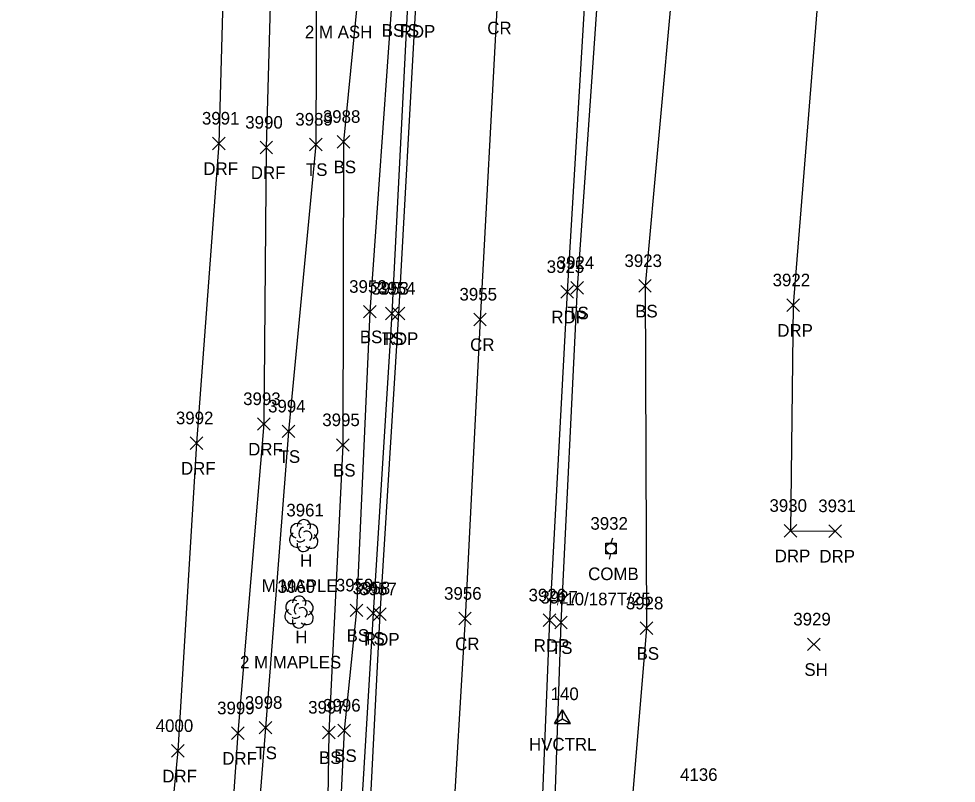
# Model space of a CAD drawing. Extents: x 1678863 to 1683592, y 407783 to 418211.
# Drawn here: x 1680263.1 to 1680411.8, y 413639.6 to 413760.9 of the extents above; entities that cross this region are included whole.
import ezdxf

# ---------------------------------------------------------------- set-up
doc = ezdxf.new("R2010")
doc.units = 0
for name, color, linetype in [('C_A', 7, 'Continuous'), ('C_I', 7, 'Continuous'), ('CPSM', 7, 'Continuous'), ('L_A', 7, 'Continuous'), ('L_C', 7, 'Continuous'), ('L_I', 7, 'Continuous'), ('L_TIC', 7, 'Continuous'), ('LELB', 7, 'Continuous'), ('LTD', 7, 'Continuous'), ('P_A', 7, 'Continuous'), ('P_I', 7, 'Continuous'), ('P_TIC', 7, 'Continuous'), ('PET', 7, 'Continuous'), ('PRC', 7, 'Continuous'), ('R_A', 7, 'Continuous'), ('R_I', 7, 'Continuous'), ('R_TIC', 7, 'Continuous'), ('RDF', 7, 'Continuous'), ('RDP', 7, 'Continuous'), ('U_A', 7, 'Continuous'), ('U_C', 7, 'Continuous'), ('U_I', 7, 'Continuous'), ('UP', 7, 'Continuous')]:
    doc.layers.add(name, color=color, linetype=linetype)

msp = doc.modelspace()

# ---------------------------------------------------------------- linework, layer by layer
at = {"layer": 'CPSM'}
for p, q in [((1680348.09, 413649.08), (1680349.34, 413651.25)), ((1680350.59, 413649.08), (1680349.34, 413651.25)), ((1680349.34, 413649.8), (1680349.34, 413651.25)), ((1680348.09, 413649.08), (1680349.34, 413649.8)), ((1680349.34, 413649.8), (1680349.34, 413649.8)), ((1680349.34, 413649.8), (1680350.59, 413649.08)), ((1680348.09, 413649.08), (1680350.59, 413649.08))]:
    msp.add_line(p, q, dxfattribs=at)
at = {"layer": 'L_TIC'}
for points in [[(1680309.23, 413739.98), (1680311.23, 413741.98)], [(1680311.23, 413739.98), (1680309.23, 413741.98)], [(1680313.59, 413740.41), (1680315.59, 413742.41)], [(1680315.59, 413740.41), (1680313.59, 413742.41)], [(1680361.43, 413717.53), (1680363.43, 413719.53)], [(1680363.43, 413717.53), (1680361.43, 413719.53)], [(1680350.69, 413717.23), (1680352.69, 413719.23)], [(1680352.69, 413717.23), (1680350.69, 413719.23)], [(1680317.76, 413713.44), (1680319.76, 413715.44)], [(1680319.76, 413713.44), (1680317.76, 413715.44)], [(1680321.28, 413713.15), (1680323.28, 413715.15)], [(1680323.28, 413713.15), (1680321.28, 413715.15)], [(1680304.9, 413694.45), (1680306.9, 413696.45)], [(1680306.9, 413694.45), (1680304.9, 413696.45)], [(1680313.5, 413692.28), (1680315.5, 413694.28)], [(1680315.5, 413692.28), (1680313.5, 413694.28)], [(1680315.65, 413666.05), (1680317.65, 413668.05)], [(1680317.65, 413666.05), (1680315.65, 413668.05)], [(1680318.32, 413665.59), (1680320.32, 413667.59)], [(1680320.32, 413665.59), (1680318.32, 413667.59)], [(1680348.1, 413664.12), (1680350.1, 413666.12)], [(1680350.1, 413664.12), (1680348.1, 413666.12)], [(1680361.65, 413663.2), (1680363.65, 413665.2)], [(1680363.65, 413663.2), (1680361.65, 413665.2)], [(1680388.22, 413660.65), (1680390.22, 413662.65)], [(1680390.22, 413660.65), (1680388.22, 413662.65)], [(1680301.22, 413647.42), (1680303.22, 413649.42)], [(1680303.22, 413647.42), (1680301.22, 413649.42)], [(1680311.26, 413646.66), (1680313.26, 413648.66)], [(1680313.26, 413646.66), (1680311.26, 413648.66)], [(1680313.69, 413646.98), (1680315.69, 413648.98)], [(1680315.69, 413646.98), (1680313.69, 413648.98)]]:
    msp.add_lwpolyline(points, dxfattribs=at)
at = {"layer": 'LELB'}
for points in [[(1680328.8, 414196.16), (1680329.42, 414154.35), (1680329.9, 414108.73), (1680324.37, 414065.09), (1680323.69, 414045.18), (1680321.93, 414011.62), (1680327.59, 413969.26), (1680329.3, 413913), (1680328.66, 413864.29), (1680326.97, 413811.9), (1680324.77, 413763.09), (1680322.28, 413714.15), (1680319.32, 413666.59), (1680317.19, 413631.47), (1680315.04, 413584.83), (1680311.9, 413541.88), (1680311.77, 413525.72)], [(1680333.49, 414185.64), (1680335.28, 414154.34), (1680335.31, 414108.58), (1680333.17, 414064.14), (1680332.9, 414010.98), (1680327.01, 414005.42), (1680327.59, 413969.26), (1680324.87, 413913.45), (1680326.11, 413864.17), (1680324.22, 413811.96), (1680322.23, 413763.08), (1680318.76, 413714.44), (1680316.65, 413667.05), (1680314.69, 413647.98), (1680313.33, 413619.55), (1680312.59, 413608.22), (1680310.92, 413608.34)], [(1680310.3, 413964.45), (1680313.38, 413925.26), (1680313.62, 413870.17), (1680310.5, 413836.3), (1680310.39, 413783.38), (1680310.23, 413740.98), (1680305.9, 413695.45), (1680302.22, 413648.42), (1680299.26, 413611.53), (1680297.37, 413601.66), (1680307.54, 413597.2), (1680308.18, 413584.58), (1680306.18, 413542.36), (1680304.07, 413518.67), (1680292.7, 413506.12)], [(1680410.49, 413871.95), (1680391.22, 413872.57), (1680366.56, 413871.7), (1680360.91, 413867.94), (1680361.47, 413861.16), (1680357.56, 413819.52), (1680355.15, 413768.47), (1680351.69, 413718.23), (1680349.1, 413665.12), (1680348.01, 413633.93), (1680345.49, 413592.28), (1680344.55, 413583.78), (1680350.55, 413572.29), (1680354.65, 413565.16)], [(1680411.8, 413856.83), (1680388.37, 413856.64), (1680367.47, 413857.06), (1680366.7, 413818.76), (1680366.79, 413766.4), (1680362.43, 413718.53), (1680362.65, 413664.2), (1680360.05, 413633.04), (1680379.39, 413591.61)], [(1680315.59, 413837.65), (1680318.63, 413782.24), (1680314.59, 413741.41), (1680314.5, 413693.28), (1680312.26, 413647.66), (1680311.86, 413619.89), (1680310.92, 413608.34)]]:
    msp.add_lwpolyline(points, dxfattribs=at)
at = {"layer": 'LTD'}
for p, q in [((1680308.28, 413678.95), (1680308.28, 413678.95)), ((1680308.28, 413678.95), (1680308.28, 413678.95)), ((1680307.53, 413666.82), (1680307.53, 413666.82)), ((1680307.53, 413666.82), (1680307.53, 413666.82))]:
    msp.add_line(p, q, dxfattribs=at)
for centre in [(1680308.32, 413680.39), (1680307.58, 413668.25)]:
    msp.add_arc(centre, 1.05, 335.5272, 180.9563, dxfattribs=at)
for centre, major_axis, ratio, start_param, end_param in [((1680307.48, 413679.62), (1.21, -0.51), 0.895232, 1.570796, 4.712389), ((1680309.32, 413679.54), (-1.14, -0.48), 0.949671, 1.570796, 4.712389), ((1680307.19, 413678.24), (0.58, -1.04), 0.959034, 3.141593, 6.283185), ((1680308.07, 413679.41), (-0.208, -0.792), 0.645439, 3.141593, 6.283185), ((1680308.78, 413678.79), (-0.5, 0.667), 0.989748, 3.141593, 6.283185), ((1680307.82, 413678.2), (-0.625, -0.083), 0.423636, 0, 3.141593), ((1680309.28, 413678.12), (-1.09, 0.79), 0.841452, 1.570796, 4.712389), ((1680308.28, 413677.45), (0.26, 1.06), 0.942809, 1.570796, 4.712389), ((1680306.74, 413667.48), (1.21, -0.51), 0.895232, 1.570796, 4.712389), ((1680307.32, 413667.28), (-0.208, -0.792), 0.645439, 3.141593, 6.283185), ((1680308.03, 413666.65), (-0.5, 0.667), 0.989748, 3.141593, 6.283185), ((1680308.57, 413667.4), (-1.14, -0.48), 0.949671, 1.570796, 4.712389), ((1680306.45, 413666.11), (0.58, -1.04), 0.959034, 3.141593, 6.283185), ((1680307.07, 413666.07), (-0.625, -0.083), 0.423636, 0, 3.141593), ((1680308.53, 413665.98), (-1.09, 0.79), 0.841452, 1.570796, 4.712389), ((1680307.53, 413665.32), (0.26, 1.06), 0.942809, 1.570796, 4.712389)]:
    msp.add_ellipse(centre, major_axis=major_axis, ratio=ratio, start_param=start_param, end_param=end_param, dxfattribs=at)
at = {"layer": 'P_TIC'}
for points in [[(1680349.09, 413716.59), (1680351.09, 413718.59)], [(1680351.09, 413716.59), (1680349.09, 413718.59)], [(1680322.35, 413713.16), (1680324.35, 413715.16)], [(1680324.35, 413713.16), (1680322.35, 413715.16)], [(1680335.26, 413712.21), (1680337.26, 413714.21)], [(1680337.26, 413712.21), (1680335.26, 413714.21)], [(1680319.37, 413665.45), (1680321.37, 413667.45)], [(1680321.37, 413665.45), (1680319.37, 413667.45)], [(1680332.88, 413664.73), (1680334.88, 413666.73)], [(1680334.88, 413664.73), (1680332.88, 413666.73)], [(1680346.28, 413664.47), (1680348.28, 413666.47)], [(1680348.28, 413664.47), (1680346.28, 413666.47)]]:
    msp.add_lwpolyline(points, dxfattribs=at)
at = {"layer": 'PET'}
for points in [[(1680337.74, 414063.85), (1680336.89, 414010.83), (1680335.53, 413968.42), (1680333.05, 413912.65), (1680330.57, 413864.02), (1680327.9, 413811.73), (1680326.03, 413762.93), (1680323.35, 413714.16), (1680320.37, 413666.45), (1680318.55, 413631.25), (1680316.14, 413584.69), (1680313.68, 413541.42), (1680312.42, 413523.36), (1680310.1, 413497.18), (1680310.27, 413479.23), (1680309.45, 413465.43), (1680306.28, 413414.4), (1680304.56, 413390.73), (1680303.5, 413367.03), (1680300.17, 413323.12), (1680296.71, 413266.44), (1680294.23, 413226.16), (1680292.89, 413196.25), (1680291.23, 413147.08)], [(1680365.04, 414025.12), (1680363.57, 413992.05), (1680361.98, 413945.68), (1680359.55, 413895.48), (1680358.76, 413869.12), (1680357.89, 413860.66), (1680355.72, 413819.25), (1680353.15, 413768.91), (1680350.09, 413717.59), (1680347.28, 413665.47), (1680345.99, 413633.9), (1680343.8, 413592.27), (1680342.77, 413574.68), (1680340.07, 413539.43), (1680339.13, 413515.37), (1680337.39, 413483.26), (1680333.74, 413422.22), (1680332.43, 413393.84), (1680331.39, 413363.68), (1680328.51, 413328.7), (1680325.07, 413264.49), (1680323.24, 413225.37), (1680321.3, 413184.73)]]:
    msp.add_lwpolyline(points, dxfattribs=at)
at = {"layer": 'PRC'}
msp.add_lwpolyline([(1680351.68, 414063.47), (1680351.07, 414011.17), (1680349.92, 413968.85), (1680347.07, 413911.41), (1680344.67, 413863.93), (1680341.49, 413810.97), (1680338.98, 413763.46), (1680336.26, 413713.21), (1680333.88, 413665.73), (1680331.73, 413629.34), (1680329.35, 413585.64), (1680326.79, 413539.67), (1680324.56, 413493.26), (1680322.55, 413462.88), (1680320.16, 413417.83), (1680318.29, 413388.45), (1680316.89, 413365.1), (1680314.19, 413322.55), (1680311.04, 413264.13), (1680308.9, 413226.32), (1680307.27, 413195.54), (1680304.84, 413145.79)], dxfattribs=at)
at = {"layer": 'R_TIC'}
for points in [[(1680293.84, 413740.14), (1680295.84, 413742.14)], [(1680295.84, 413740.14), (1680293.84, 413742.14)], [(1680301.36, 413739.49), (1680303.36, 413741.49)], [(1680303.36, 413739.49), (1680301.36, 413741.49)], [(1680384.93, 413714.47), (1680386.93, 413716.47)], [(1680386.93, 413714.47), (1680384.93, 413716.47)], [(1680300.95, 413695.62), (1680302.95, 413697.62)], [(1680302.95, 413695.62), (1680300.95, 413697.62)], [(1680290.28, 413692.58), (1680292.28, 413694.58)], [(1680292.28, 413692.58), (1680290.28, 413694.58)], [(1680384.52, 413678.68), (1680386.52, 413680.68)], [(1680386.52, 413678.68), (1680384.52, 413680.68)], [(1680391.6, 413678.63), (1680393.6, 413680.63)], [(1680393.6, 413678.63), (1680391.6, 413680.63)], [(1680296.83, 413646.55), (1680298.83, 413648.55)], [(1680298.83, 413646.55), (1680296.83, 413648.55)], [(1680287.32, 413643.74), (1680289.32, 413645.74)], [(1680289.32, 413643.74), (1680287.32, 413645.74)]]:
    msp.add_lwpolyline(points, dxfattribs=at)
at = {"layer": 'RDF'}
for points in [[(1680293.38, 413994.57), (1680304.05, 413962.38), (1680306.31, 413925.24), (1680306.07, 413871.28), (1680307.56, 413836.62), (1680303.79, 413791.26), (1680302.36, 413740.49), (1680301.95, 413696.62), (1680297.83, 413647.55), (1680295.14, 413608.28), (1680287.08, 413579.47)], [(1680285.71, 413990.78), (1680295.95, 413964.17), (1680298.49, 413925.92), (1680297.85, 413873.11), (1680298.81, 413841.35), (1680296.33, 413794.3), (1680294.84, 413741.14), (1680291.28, 413693.58), (1680288.32, 413644.74), (1680285.28, 413613.34), (1680275.4, 413582.62), (1680263.09, 413554.99)]]:
    msp.add_lwpolyline(points, dxfattribs=at)
at = {"layer": 'RDP'}
msp.add_lwpolyline([(1680410.39, 413843.14), (1680396.21, 413836.2), (1680392.99, 413818.96), (1680390.07, 413766.83), (1680385.93, 413715.47), (1680385.52, 413679.68), (1680392.6, 413679.63)], dxfattribs=at)
at = {"layer": 'UP'}
for p, q in [((1680357.28, 413678.51), (1680357.03, 413677.68)), ((1680356.19, 413676.01), (1680356.19, 413677.68)), ((1680356.19, 413677.68), (1680357.86, 413677.68)), ((1680357.03, 413676.84), (1680357.03, 413676.84)), ((1680357.86, 413677.68), (1680357.86, 413676.01)), ((1680357.86, 413676.01), (1680356.19, 413676.01)), ((1680356.78, 413675.18), (1680357.03, 413676.01))]:
    msp.add_line(p, q, dxfattribs=at)
msp.add_circle((1680357.03, 413676.84), 0.833, dxfattribs=at)

# ---------------------------------------------------------------- texts
at = {"layer": 'C_A'}
msp.add_text('HVCTRL', height=2, dxfattribs=at).set_placement((1680344.03, 413644.8))
at = {"layer": 'C_I'}
msp.add_text('140', height=2, dxfattribs=at).set_placement((1680347.46, 413652.8))
at = {"layer": 'L_A'}
for s, p in [('BS', (1680320.67, 413758.08)), ('TS', (1680323.18, 413758.09)), ('TS', (1680308.64, 413735.98)), ('BS', (1680313.03, 413736.41)), ('TS', (1680350.1, 413713.23)), ('BS', (1680360.87, 413713.53)), ('BS', (1680317.2, 413709.44)), ('TS', (1680320.69, 413709.15)), ('TS', (1680304.31, 413690.45)), ('BS', (1680312.95, 413688.28)), ('H', (1680307.71, 413673.95)), ('H', (1680306.96, 413661.82)), ('BS', (1680315.09, 413662.05)), ('TS', (1680317.73, 413661.59)), ('TS', (1680347.51, 413660.12)), ('BS', (1680361.09, 413659.2)), ('SH', (1680387.71, 413656.65)), ('TS', (1680300.63, 413643.42)), ('BS', (1680313.13, 413642.98)), ('BS', (1680310.71, 413642.66))]:
    msp.add_text(s, height=2, dxfattribs=at).set_placement(p)
at = {"layer": 'L_C'}
for s, p in [('2 M ASH', (1680308.48, 413757.84)), ('M MAPLE', (1680301.63, 413669.95)), ('2 M MAPLES', (1680298.19, 413657.82))]:
    msp.add_text(s, height=2, dxfattribs=at).set_placement(p)
at = {"layer": 'L_I'}
for s, p in [('3988', (1680311.33, 413744.41)), ('3989', (1680306.96, 413743.98)), ('3924', (1680348.43, 413721.23)), ('3923', (1680359.17, 413721.53)), ('3952', (1680315.5, 413717.44)), ('3953', (1680319.02, 413717.15)), ('3994', (1680302.64, 413698.45)), ('3995', (1680311.24, 413696.28)), ('3961', (1680305.54, 413681.95)), ('3960', (1680304.14, 413669.82)), ('3959', (1680313.39, 413670.05)), ('3958', (1680316.06, 413669.59)), ('3927', (1680345.84, 413668.12)), ('3928', (1680359.39, 413667.2)), ('3929', (1680385.95, 413664.65)), ('3998', (1680298.96, 413651.42)), ('3997', (1680309, 413650.66)), ('3996', (1680311.37, 413650.98)), ('4136', (1680367.99, 413639.98))]:
    msp.add_text(s, height=2, dxfattribs=at).set_placement(p)
at = {"layer": 'P_A'}
for s, p in [('RDP', (1680323.52, 413757.93)), ('CR', (1680337.41, 413758.46)), ('RDP', (1680347.58, 413712.59)), ('RDP', (1680320.83, 413709.16)), ('CR', (1680334.69, 413708.21)), ('RDP', (1680317.86, 413661.45)), ('CR', (1680332.31, 413660.73)), ('RDP', (1680344.77, 413660.47))]:
    msp.add_text(s, height=2, dxfattribs=at).set_placement(p)
at = {"layer": 'P_I'}
for s, p in [('3925', (1680346.83, 413720.59)), ('3954', (1680320.09, 413717.16)), ('3955', (1680333, 413716.21)), ('3957', (1680317.11, 413669.45)), ('3956', (1680330.56, 413668.73)), ('3926', (1680343.96, 413668.47))]:
    msp.add_text(s, height=2, dxfattribs=at).set_placement(p)
at = {"layer": 'R_A'}
for s, p in [('DRF', (1680292.38, 413736.14)), ('DRF', (1680299.9, 413735.49)), ('DRP', (1680383.41, 413710.47)), ('DRF', (1680299.48, 413691.62)), ('DRF', (1680288.82, 413688.58)), ('DRP', (1680383.01, 413674.68)), ('DRP', (1680390.09, 413674.63)), ('DRF', (1680295.37, 413642.55)), ('DRF', (1680285.86, 413639.74))]:
    msp.add_text(s, height=2, dxfattribs=at).set_placement(p)
at = {"layer": 'R_I'}
for s, p in [('3991', (1680292.15, 413744.14)), ('3990', (1680299.02, 413743.49)), ('3922', (1680382.67, 413718.47)), ('3993', (1680298.69, 413699.62)), ('3992', (1680288.02, 413696.58)), ('3930', (1680382.17, 413682.68)), ('3931', (1680389.91, 413682.63)), ('3999', (1680294.56, 413650.55)), ('4000', (1680284.82, 413647.74))]:
    msp.add_text(s, height=2, dxfattribs=at).set_placement(p)
at = {"layer": 'U_A'}
msp.add_text('COMB', height=2, dxfattribs=at).set_placement((1680353.41, 413671.84))
at = {"layer": 'U_C'}
msp.add_text('#10/187T/25', height=2, dxfattribs=at).set_placement((1680348.3, 413667.84))
at = {"layer": 'U_I'}
msp.add_text('3932', height=2, dxfattribs=at).set_placement((1680353.77, 413679.84))

doc.saveas('drawing.dxf')
